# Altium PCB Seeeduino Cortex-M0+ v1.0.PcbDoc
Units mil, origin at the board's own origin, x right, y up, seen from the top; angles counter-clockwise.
Board outline 2700 x 2100 mil, 2 copper layers (Top, Bottom); 98 components, 76 nets, 339 pads, 260 vias.
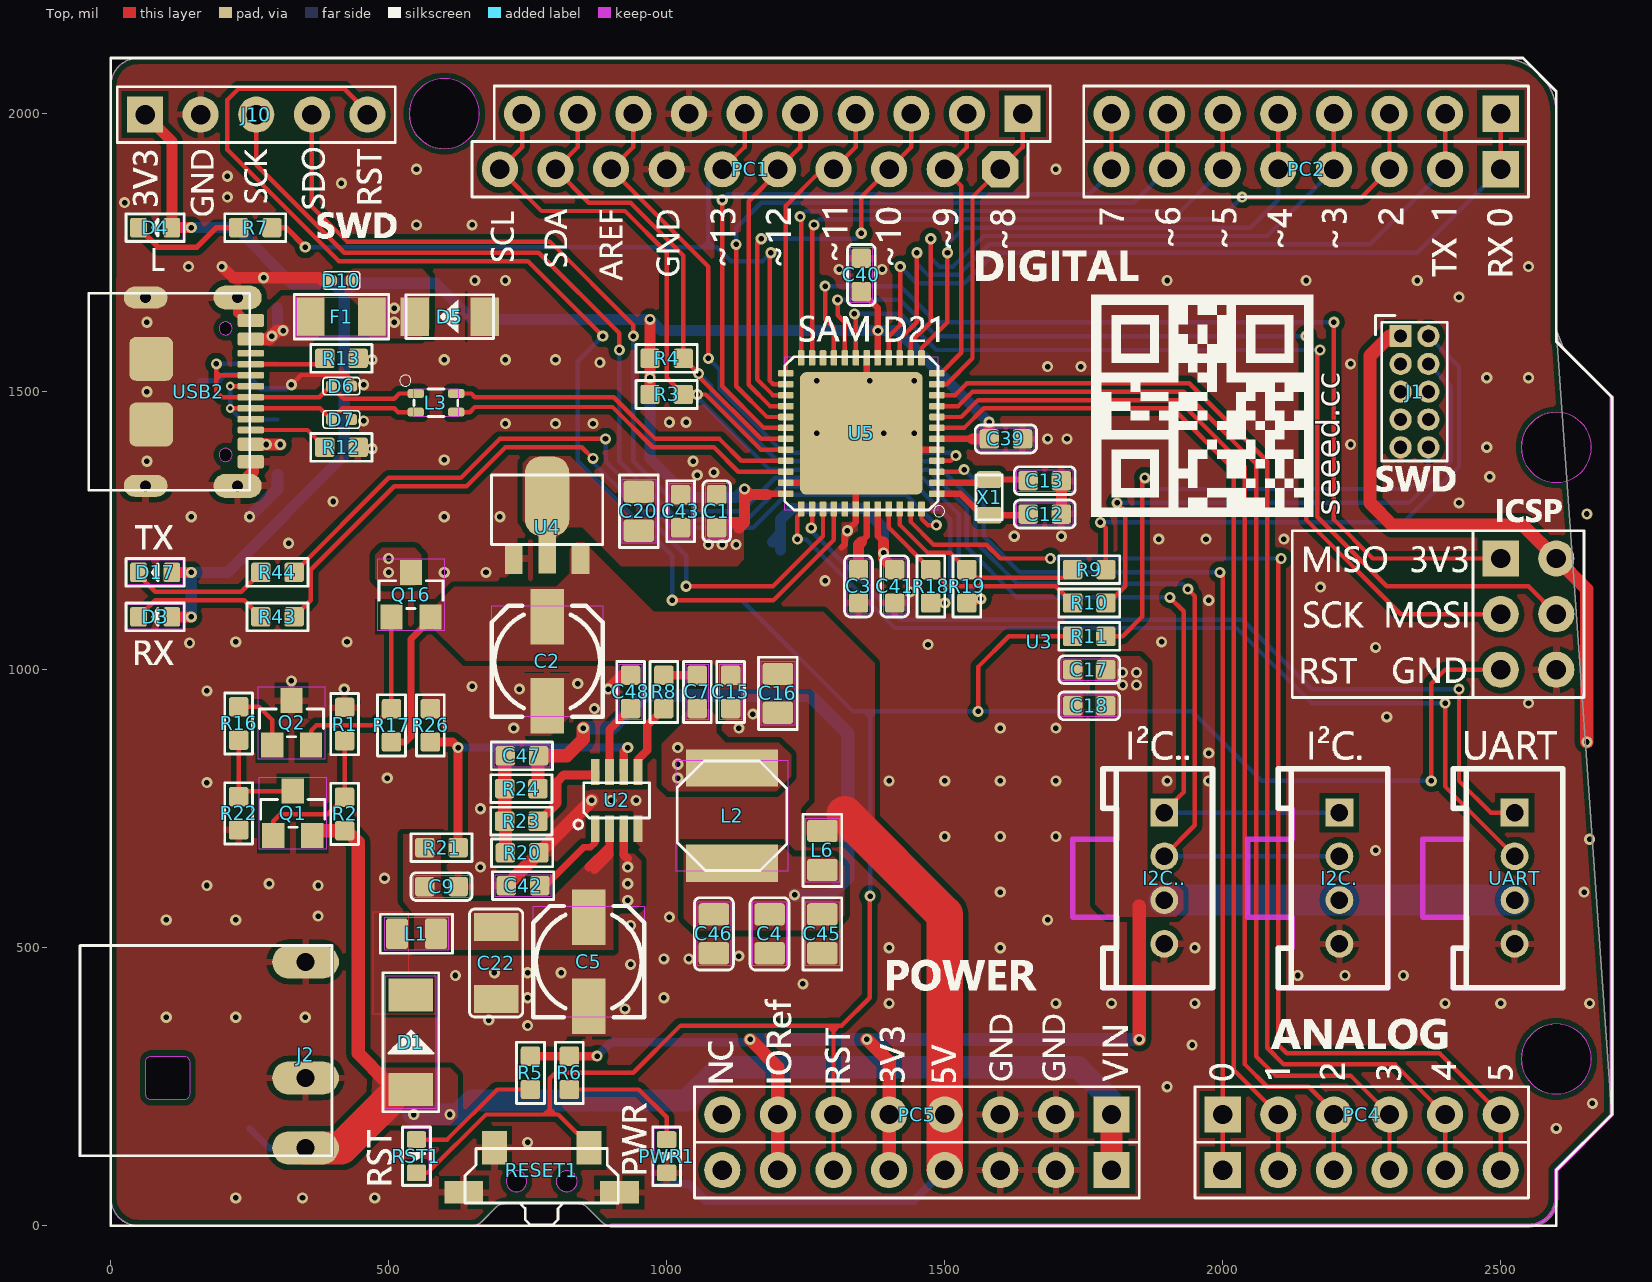
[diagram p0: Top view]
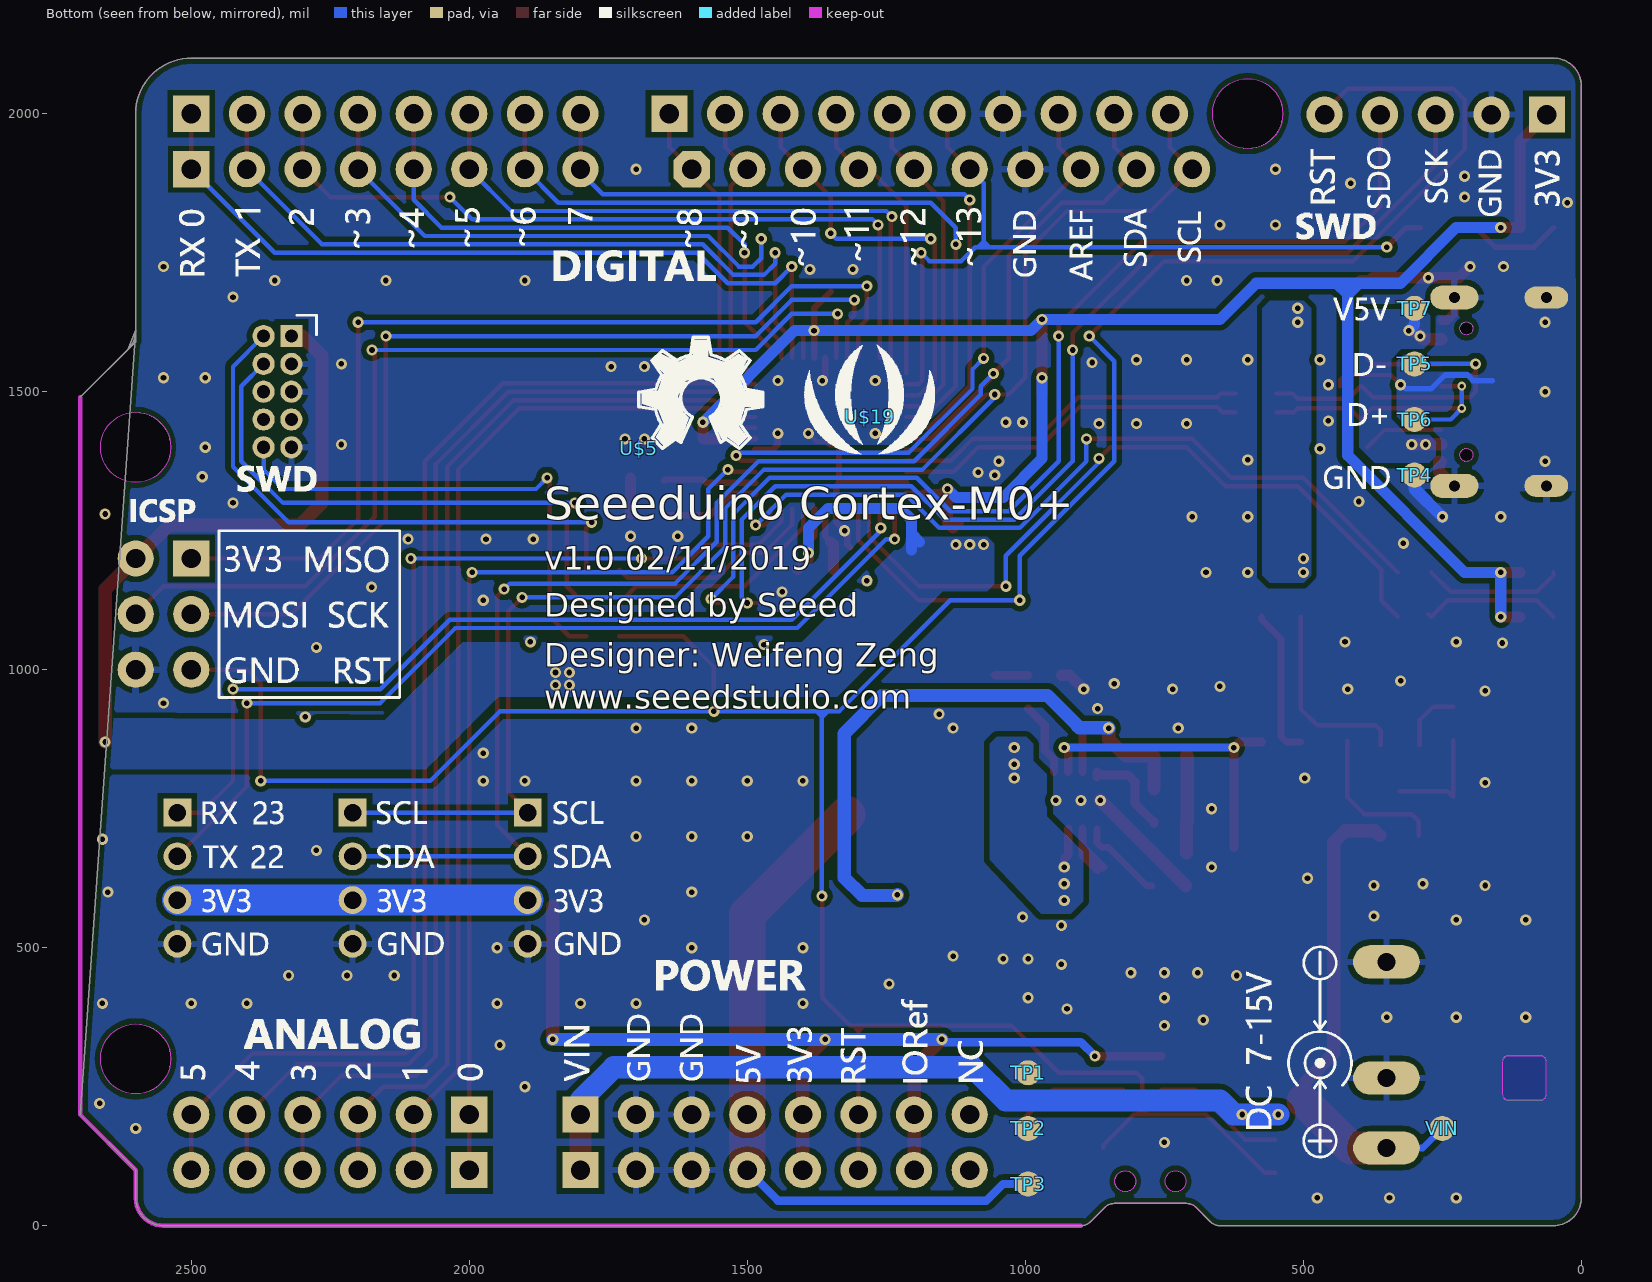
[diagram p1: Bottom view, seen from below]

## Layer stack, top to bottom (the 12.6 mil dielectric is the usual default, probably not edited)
Top Solder: solder mask 0.4, Solder Resist, Dk 3.5
Top: signal copper 1.378
Dielectric 1: dielectric 12.6, FR-4, Dk 4.8
Bottom: signal copper 1.378
Bottom Solder: solder mask 0.4, Solder Resist, Dk 3.5

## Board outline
2600,1610.71 ccw(c2650,1610.71) 2614.65,1575.35 2700,1490 2600,1590 2600,2000 ccw(c2500,2000) 2500,2100 50,2100 ccw(c50,2050) 0,2050 0,50 ccw(c50,50) 50,0 649.64,0 ccw(c649.64,25) 667.32,7.32 692.68,32.68 cw(c710.36,15) 710.36,40 839.64,40 cw(c839.64,15) 857.32,32.68 882.68,7.32 ccw(c900.36,25) 900.36,0 2550,0 ccw(c2550,50) 2600,50 2600,100 2700,200 2600,1610.71 ccw(c2650,1610.71)
cut-out: 600,1937 ccw(c600,2000) 663,2000 ccw(c600,2000) 600,2063 ccw(c600,2000) 537,2000 ccw(c600,2000)
cut-out: 2600,1337 ccw(c2600,1400) 2663,1400 ccw(c2600,1400) 2600,1463 ccw(c2600,1400) 2537,1400 ccw(c2600,1400)
cut-out: 2600,237 ccw(c2600,300) 2663,300 ccw(c2600,300) 2600,363 ccw(c2600,300) 2537,300 ccw(c2600,300)
cut-out: 73.11,226.42 cw(c73.11,236.42) 63.11,236.42 63.11,295.16 cw(c73.11,295.16) 73.11,305.16 131.85,305.16 cw(c131.85,295.16) 141.85,295.16 141.85,236.42 cw(c131.85,236.42) 131.85,226.42
cut-out: 729.72,61.3 ccw(c729.72,80) 748.42,80 ccw(c729.72,80) 729.72,98.7 ccw(c729.72,80) 711.02,80 ccw(c729.72,80)
cut-out: 820.28,61.3 ccw(c820.28,80) 838.98,80 ccw(c820.28,80) 820.28,98.7 ccw(c820.28,80) 801.58,80 ccw(c820.28,80)
cut-out: 206.69,1374.41 ccw(c206.69,1386.22) 218.5,1386.22 ccw(c206.69,1386.22) 206.69,1398.03 ccw(c206.69,1386.22) 194.88,1386.22 ccw(c206.69,1386.22)
cut-out: 206.69,1601.97 ccw(c206.69,1613.78) 218.5,1613.78 ccw(c206.69,1613.78) 206.69,1625.59 ccw(c206.69,1613.78) 194.88,1613.78 ccw(c206.69,1613.78)

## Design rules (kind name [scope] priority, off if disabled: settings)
BoardOutlineClearance mdCopperDimension [All] p1: gap=10 ignorepadtopadclearanceinfootprint=FALSE except(0: Arc-SplitContinuation Track-SplitContinuation SMDPad-SplitContinuation THPad-SplitContinuation Via-SplitContinuation Fill-SplitContinuation Poly-SplitContinuation Region-SplitContinuation Text-SplitContinuation)
Clearance Clearance_for_PolygonClass_Isolate_10 [InPolygonClass('Isolate_10') vs IsArc Or IsTrack Or IsPad Or IsVia Or IsFill Or IsRegion Or IsText] p1: gap=10 ignorepadtopadclearanceinfootprint=FALSE
Clearance "Clearance (Same Net)" [All] p2: gap=6 ignorepadtopadclearanceinfootprint=FALSE
Clearance Clearance_for_NetClass_usbvcc [InNetClass('usbvcc') vs InNetClass('usbvcc')] p3: gap=6 ignorepadtopadclearanceinfootprint=FALSE
Clearance Clearance_for_NetClass_gnd [InNetClass('gnd') vs InNetClass('gnd')] p4: gap=6 ignorepadtopadclearanceinfootprint=FALSE
Clearance Clearance_for_NetClass_power [InNetClass('power') vs InNetClass('power')] p5: gap=6 ignorepadtopadclearanceinfootprint=FALSE
Clearance [All] p6: gap=6 ignorepadtopadclearanceinfootprint=FALSE
HoleSize HoleSize_For_NetClass_usbvcc [InNetClass('usbvcc')] p1: absolutevalues=TRUE maxlimit=6 minlimit=6 maxpercent=80.000 minpercent=20.000
HoleSize HoleSize_For_NetClass_gnd [InNetClass('gnd')] p2: absolutevalues=TRUE maxlimit=6 minlimit=6 maxpercent=80.000 minpercent=20.000
HoleSize HoleSize_For_NetClass_power [InNetClass('power')] p3: absolutevalues=TRUE maxlimit=6 minlimit=6 maxpercent=80.000 minpercent=20.000
HoleSize [All] p4: absolutevalues=TRUE maxlimit=100000 minlimit=8 maxpercent=80.000 minpercent=20.000
HoleToHoleClearance mdDrill [All] p1: gap=10 allowstackedmicrovias=TRUE
MinimumSolderMaskSliver [All] p1 off: minsoldermaskwidth=10
PasteMaskExpansion Expansion_SMDPaste_OFF [InPadClass('SMDPaste_OFF')] p1: expansion=0
PasteMaskExpansion mlMinCreamFrame [All] p2: expansion=0
PolygonConnect PolygonConnect_For_PolygonThermal_ON_Width80000_Gap100000 [InPolygonClass('PolygonThermal_ON_Width80000_Gap100000') vs Not IsVia] p1: connectstyle=Relief reliefconductorwidth=8 reliefentries=4 polygonreliefangle="90 Angle" airgapwidth=10
PolygonConnect PolygonConnect_For_PolygonThermal_ON_Width120000_Gap100000 [InPolygonClass('PolygonThermal_ON_Width120000_Gap100000') vs Not IsVia] p2: connectstyle=Relief reliefconductorwidth=12 reliefentries=4 polygonreliefangle="90 Angle" airgapwidth=10
PolygonConnect PolygonConnect_For_PolygonThermal_OFF [InPolygonClass('PolygonThermal_OFF')] p3: connectstyle=Direct reliefconductorwidth=10 reliefentries=4 polygonreliefangle="90 Angle" airgapwidth=10
PolygonConnect ThermalVias [IsVia] p4: connectstyle=Direct reliefconductorwidth=10 reliefentries=4 polygonreliefangle="90 Angle" airgapwidth=10
PolygonConnect [All] p5: connectstyle=Relief reliefconductorwidth=10 reliefentries=4 polygonreliefangle="90 Angle" airgapwidth=10
RoutingVias [All] p1: holewidth=8 width=16 viastyle="Through Hole" minholewidth=8 minwidth=16 maxholewidth=100 maxwidth=100
SolderMaskExpansion Expansion_SMDSolder_OFF [InPadClass('SMDSolder_OFF')] p1: expansion=0
SolderMaskExpansion mlMinStopFrame [All] p2: expansion=2
Width Width_For_NetClass_usbvcc [InNetClass('usbvcc')] p1: maxlimit=10 minlimit=6 preferedwidth=6
Width Width_For_NetClass_gnd [InNetClass('gnd')] p2: maxlimit=10 minlimit=6 preferedwidth=6
Width Width_For_NetClass_power [InNetClass('power')] p3: maxlimit=10 minlimit=6 preferedwidth=6
Width [All] p4: maxlimit=10000 minlimit=6 preferedwidth=6
26 further rules are at their usual default settings.

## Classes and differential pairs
polygon class PolygonThermal_ON_Width80000_Gap100000: Polygon_1_Net_3V3 Polygon_3_Net_N$23
polygon class PolygonThermal_ON_Width120000_Gap100000: Polygon_3_Net_GND Polygon_7_Net_GND
polygon class PolygonThermal_OFF: Polygon_1_Net_5V Polygon_1_Net_EXT_PWR Polygon_1_Net_GND Polygon_1_Net_N$10 Polygon_1_Net_N$23 Polygon_1_Net_OUT1 Polygon_1_Net_PWR_IN Polygon_1_Net_USB5V Polygon_1_Net_V_USB Polygon_2_Net_3V3 Polygon_2_Net_GND Polygon_2_Net_N$23 Polygon_2_Net_USB5V Polygon_2_Net_V_USB Polygon_3_Net_3V3 Polygon_3_Net_USB5V Polygon_4_Net_GND Polygon_5_Net_GND Polygon_6_Net_GND Polygon_8_Net_GND Polygon_9_Net_GND Polygon_10_Net_GND Polygon_11_Net_GND
polygon class Isolate_10: Polygon_1_Net_3V3 Polygon_1_Net_5V Polygon_1_Net_EXT_PWR Polygon_1_Net_GND Polygon_1_Net_N$10 Polygon_1_Net_N$23 Polygon_1_Net_OUT1 Polygon_1_Net_PWR_IN Polygon_1_Net_USB5V Polygon_1_Net_V_USB Polygon_2_Net_3V3 Polygon_2_Net_GND Polygon_2_Net_N$23 Polygon_2_Net_USB5V Polygon_2_Net_V_USB Polygon_3_Net_3V3 Polygon_3_Net_GND Polygon_3_Net_N$23 Polygon_3_Net_USB5V Polygon_4_Net_GND Polygon_5_Net_GND Polygon_6_Net_GND Polygon_7_Net_GND Polygon_10_Net_GND Polygon_11_Net_GND
pad class SMDSolder_OFF: U4-2
pad class SMDPaste_OFF: TP1-T TP2-T TP3-T TP4-T TP5-T TP6-T TP7-T U4-2 U5-PAD VIN-T

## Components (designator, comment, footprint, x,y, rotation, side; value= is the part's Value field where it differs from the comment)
C1 "100nF" C0603#1 1090,1285 r0 top
C2 "22uF" ELECTRO-SMD-B-4.8MM 785,1015 r90 top
C3 "1uF" C0603#1 1345,1150 r180 top
C4 "10uF" C0805#1 1185,525 r180 top
C5 "22uF" ELECTRO-SMD-B-4.8MM 860,475 r90 top
C7 "100nF" C0603#2 1055,960 r90 top
C9 "100nF" C0603#1 595,610 r270 top
C12 "22p" C0603#1 1680,1280 r90 top
C13 "22p" C0603#1 1680,1340 r90 top
C15 "100nF" C0603#2 1115,960 r270 top
C16 "10uF" C0805#2 1200,957.5 r270 top
C17 "100nF" C0603#1 1760,1000 r90 top
C18 "1uF" C0603#1 1760,935 r90 top
C20 "10uF" C0805#2 950,1285 r90 top
C22 "22uF_16V" C1206 693.3,472.5 r270 top
C39 "100nF" C0603#1 1610,1415 r270 top
C40 "100nF" C0603#1 1350,1710 r0 top
C41 "100nF" C0603#1 1410,1150 r180 top
C42 "22nF" C0603#2 741.8,611.6 r0 top
C43 "100nF" C0603#2 1025,1285 r270 top
C45 "10uF" C0805#2 1280,525 r90 top
C46 "10uF" C0805#1 1085,525 r180 top
C47 "DNP" C0603#2 739.6,845 r180 top
C48 "100nF" C0603#2 935,960 r270 top
D1 "1N5819" D2010 540,330 r90 top
D3 "RED" LED-0603 80,1095 r0 top
D4 "BLUE" LED-0603 80,1795 r0 top
D5 "BZV55-C5V1" SOD80C 610,1635 r0 top
D6 "ESDPSA0402V05" ESD-0402 415,1510 r180 top
D7 "ESDPSA0402V05" ESD-0402 415,1450 r180 top
D10 "ESDPSA0402V05" ESD-0402 415,1700 r0 top
D17 "RED" LED-0603 80,1175 r0 top
F1 "1000mA" F1206 415,1635 r0 top
I2C. "4P-LEADED-2.0" 4P-LEADED-2.0 2210,625 r270 top
I2C.. "4P-LEADED-2.0" 4P-LEADED-2.0 1895,625 r270 top
J1 "DNP" H2X5-1.27 2345,1550 r0 top
J2 "DC JACK" DCJ3P-11.6X9.6X7.0MM -55,315 r270 top
J10 "DNP" H5-2.54 261.8,1998.4 r90 top
L1 "470R,2A" L0805 550,525 r0 top
L2 "10uH" L5040S 1117.5,737.5 r0 top
L3 "SRF2012-900YA" INT4-0.85-2X1.25X1.2MM 585,1480 r270 top
L6 "470R,2A" L0805 1280,675 r90 top
PC1 "DNP" 10P-2.54 1150,1900 r270 top
PC2 "DNP" 8P-2.54 2150,1900 r270 top
PC4 "DNP" 6P-2.54-65/35MIL 2250,200 r90 top
PC5 "DNP" 8P-2.54 1450,200 r270 top
PWR1 "GREEN" LED-0603 1000,125 r90 top
Q1 "MMBT3906LT3G" SOT23 327.6,741.7 r0 top
Q2 "MMBT3906LT3G" SOT23 325.4,904.4 r0 top
Q16 "CJ2305" SOT23 540,1135 r0 top
R1 "30K" R0603#1 420.7,902.2 r90 top
R2 "3.3K" R0603#1 420.7,740.6 r90 top
R3 "DNP" R0603#2 1000,1495 r180 top
R4 "DNP" R0603#2 1000,1560 r0 top
R5 "1k" R0603#2 755,275 r270 top
R6 "1k" R0603#2 825,275 r270 top
R7 "2k" R0603#2 260,1795 r180 top
R8 "10R" R0603#1 995,960 r90 top
R9 "0R" R0603#2 1760,1180 r0 top
R10 "0R" R0603#2 1760,1120 r0 top
R11 "0R" R0603#2 1760,1060 r0 top
R12 "5.1k" R0603#2 415,1400 r180 top
R13 "5.1k" R0603#2 415,1560 r0 top
R16 "1k" R0603#1 230.1,903.3 r90 top
R17 "100K" R0603#1 505,900 r270 top
R18 "0R" R0603#2 1475,1150 r90 top
R19 "0R" R0603#2 1540,1150 r90 top
R20 "7.5k_1%" R0603#1 740,670.7 r180 top
R21 "100K" R0603#1 595,680 r180 top
R22 "10K" R0603#1 230.1,741.7 r270 top
R23 "33k" R0603#1 738.5,727.5 r180 top
R24 "39k_1%" R0603#1 738.5,786.1 r180 top
R26 "24K" R0603#1 575,900 r90 top
R43 "2k" R0603#2 300,1095 r180 top
R44 "2k" R0603#2 300,1175 r180 top
RESET1 "TS-118E" 4P-SMD-7X3.5X3.5H 775,80 r0 top
RST1 "RED" LED-0603 550,125 r90 top
TP1 "" TP-D45MIL 995,275 r270 bottom
TP2 "" TP-D45MIL 995,175 r270 bottom
TP3 "" TP-D45MIL 995,75 r270 bottom
TP4 "" TP-D45MIL 300,1350 r180 bottom
TP5 "" TP-D45MIL 300,1550 r180 bottom
TP6 "" TP-D45MIL 300,1450 r180 bottom
TP7 "" TP-D45MIL 300,1650 r180 bottom
U2 "" TSOT23-8 910,765 r0 top
U3 "" ARDUINO-38P 0,0 r0 top
U4 "CJA1117B-3.3" SOT-89 785,1275 r0 top
U5 "MCU-ATSAMD21-QFN48" QFN48-7X7 1350,1425 r180 top
U$1 "" SEEEDSTUDIO-PCB-FRAME -361.1,-315 r0 top
U$5 "" OSHW_FILLX200_NOTEXT 1695,1398 r180 bottom
U$6 "" SEEEDSTUDIO-PCB-FRAME -364.78,-1310 r0 top
U$8 "" SEEEDSTUDIO-PCB-FRAME -358.55,-950 r0 top
U$19 "" SEEED-SILK-TNAME-280*268MIL 1280,1455 r180 bottom
U$23 "" SEEEDSTUDIO-PCB-FRAME -362.33,-610 r0 top
UART "4P-LEADED-2.0" 4P-LEADED-2.0 2525,625 r270 top
USB2 "TypeC" USB2.0-TYPE-C 250,1500 r0 top
VIN "" TP-D45MIL 250,175 r180 bottom
X1 "32,768Khz_SMD" X2-SMD-L2.0X1.2X0.55MM 1580,1310 r270 top

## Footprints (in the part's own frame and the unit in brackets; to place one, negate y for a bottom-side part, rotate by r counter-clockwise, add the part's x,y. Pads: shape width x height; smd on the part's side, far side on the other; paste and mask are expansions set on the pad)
4P-LEADED-2.0 [mil] "4P-LEADED-2.0"
  rect 50x50 / inner rect 60x60 / far side rect 50x50 hole 31.5: 1(-118.11,0)
  round 50 / inner round 60 / far side round 50 hole 31.5: 2(-39.37,0) 3(39.37,0) 4(118.11,0)
  Top keep-out lines w10: 196.85,-110.24 196.85,86.61 -196.85,86.61 -196.85,-110.24 ; 195,-110 125,-110 125,-85 70,-85 70,-165 -70,-165 -70,-85 -125,-85 -125,-110 -195,-110
  silkscreen extent -197,-110 197,87
4P-SMD-7X3.5X3.5H [mil] "4P-SMD-7X3.5X3.5H"
  rect 45x60 smd: 1(-85,60) 2(85,60)
  rect 70x40 smd: S1(-140,-20) S2(140,-20)
  silkscreen extent -138,-79 138,59
6P-2.54-65/35MIL [mil] "6P-2.54-65/35MIL"
  rect 65x65 / inner rect 60x60 / far side rect 65x65 hole 35: 1(0,250)
  round 65 / inner round 60 / far side round 65 hole 35: 2(0,150) 3(0,50) 4(0,-50) 5(0,-150) 6(0,-250)
  Top keep-out region: -50,-300 -50,300 50,300 50,-300
  Top keep-out lines w0: -50,300 -50,-300 50,-300 50,300 -50,300
  silkscreen extent -50,-300 50,300
8P-2.54 [mil] "8P-2.54"
  rect 65x65 / inner rect 60x60 / far side rect 65x65 hole 35: 1(0,350)
  round 65 / inner round 60 / far side round 65 hole 35: 2(0,250) 3(0,150) 4(0,50) 5(0,-50) 6(0,-150) 7(0,-250) 8(0,-350)
  Top keep-out region: -50,-400 -50,400 50,400 50,-400
  Top keep-out lines w0: 50,-400 -50,-400 -50,400 50,400 50,-400
  silkscreen extent -50,-400 50,400
10P-2.54 [mil] "10P-2.54"
  oct 65x65 / inner oct 60x60 / far side oct 65x65 hole 35: 1(0,450)
  round 65 / inner round 60 / far side round 65 hole 35: 2(0,350) 3(0,250) 4(0,150) 5(0,50) 6(0,-50) 7(0,-150) 8(0,-250) 9(0,-350) 10(0,-450)
  Top keep-out region: -50,-500 -50,500 50,500 50,-500
  Top keep-out lines w0: 50,-500 -50,-500 -50,500 50,500 50,-500
  silkscreen extent -50,-500 50,500
ARDUINO-38P [mil] "ARDUINO-38P"
  rect 65x65 / inner rect 60x60 / far side rect 65x65 hole 35: 1(2500,2000) 9(1640,2000) 19(2000,100) 25(1800,100) 38(2500,1200)
  round 65 / inner round 60 / far side round 65 hole 35: 2(2400,2000) 3(2300,2000) 4(2200,2000) 5(2100,2000) 6(2000,2000) 7(1900,2000) 8(1800,2000) 10(1540,2000) 11(1440,2000) 12(1340,2000) 13(1240,2000) 14(1140,2000) 15(1040,2000) 16(940,2000) 17(840,2000) 18(740,2000) 20(2100,100) 21(2200,100) 22(2300,100) 23(2400,100) 24(2500,100) 26(1700,100) 27(1600,100) 28(1500,100) 29(1400,100) 30(1300,100) 31(1200,100) 32(1100,100) 33(2600,1200) 34(2600,1100) 35(2600,1000) 36(2500,1000) 37(2500,1100)
  silkscreen extent 0,0 2700,2100
C0603#1 [mil] "C0603"
  rrect25% 35x35 smd: 1(0,30) 2(0,-30)
  Top keep-out region: -20,50 20,50 20,-50 -20,-50
  silkscreen extent -25,-55 25,55
C0603#2 [mil] "C0603"
  rrect25% 35x35 smd: 1(-30,0) 2(30,0)
  Top keep-out region: -50,-20 -50,20 50,20 50,-20
  silkscreen extent -55,-25 55,25
C0805#1 [mil] "C0805"
  rrect25% 55x40 smd: 1(0,35) 2(0,-35)
  Top keep-out region: -30,57.5 30,57.5 30,-57.5 -30,-57.5
  silkscreen extent -35,-65 35,65
C0805#2 [mil] "C0805"
  rrect25% 40x55 smd: 1(-35,0) 2(35,0)
  Top keep-out region: -57.5,-30 -57.5,30 57.5,30 57.5,-30
  silkscreen extent -65,-35 65,35
C1206 [mil] "C1206"
  rect 50x80 smd: 1(-65,0) 2(65,0)
  silkscreen extent -97,-48 97,48
D2010 [mil] "D2010"
  rect 60x80 smd: +(-85,0) -(85,0)
  Top keep-out region: -120,-45 -120,45 120,45 120,-45
  silkscreen extent -125,-50 125,50
DCJ3P-11.6X9.6X7.0MM [mil] "DCJ3P-11.6X9.6X7.0MM"
  oval 60x120 / inner round 60 / far side oval 60x120 hole 32: +(175.2,405.51) -(-159.45,405.51) CDN(49.21,405.51)
  Top keep-out region: -190,0 -190,455 190,455 190,0
  silkscreen extent -189,0 189,453
ELECTRO-SMD-B-4.8MM [mil] "ELECTRO-SMD-B-4.8MM"
  rect 100x60 smd: +(80,0) -(-80,0)
  Top keep-out region: -100,-100 -100,100 100,100 100,-100
  silkscreen extent -100,-100 100,100
ESD-0402 [mil] "ESD-0402"
  rrect50% 19.69x19.69 smd: 1(-18.21,0) 2(18.21,0)
  silkscreen extent -33,-16 33,16
F1206 [mil] "F1206"
  rect 50x70 smd: 1(-55,0) 2(55,0)
  Top keep-out region: -80,-35 -80,35 80,35 80,-35
  silkscreen extent -85,-40 85,40
H2X5-1.27 [mil] "H2X5-1.27"
  rect 39.92x39.92 / inner rect 60x60 / far side rect 39.92x39.92 hole 23.62: 1(-25,50)
  round 39.92 / inner round 60 / far side round 39.92 hole 23.62: 2(25,50) 3(-25,0) 4(25,0) 5(-25,-50) 6(25,-50) 7(-25,-100) 8(25,-100) 9(-25,-150) 10(25,-150)
  Top keep-out region: -60,-175 -60,75 60,75 60,-175
  silkscreen extent -59,-175 59,75
H5-2.54 [mil] "H5-2.54"
  rect 65x65 / inner rect 60x60 / far side rect 65x65 hole 35: 1(0,200)
  round 65 / inner round 60 / far side round 65 hole 35: 2(0,100) 3(0,0) 4(0,-100) 5(0,-200)
  Top keep-out region: -50,-250 -50,250 50,250 50,-250
  Top keep-out lines w0: -50,250 -50,-250 50,-250 50,250 -50,250
  silkscreen extent -50,-250 50,250
INT4-0.85-2X1.25X1.2MM [mil] "INT4-0.85-2X1.25X1.2MM"
  rrect50% 15.75x29.53 smd: 1(-16.73,-36.42) 2(-16.73,36.42) 3(16.73,36.42) 4(16.73,-36.42)
  Top keep-out region: 25,-40 -25,-40 -25,40 25,40
  silkscreen extent -50,-65 25,39
L0805 [mil] "L0805"
  rrect25% 40x55 smd: 1(-35,0) 2(35,0)
  Top keep-out region: -57.5,-30 -57.5,30 57.5,30 57.5,-30
  silkscreen extent -65,-35 65,35
L5040S [mm] "L5040S"
  rect 4.2x1.7 smd: 1(0,2.175) 2(0,-2.175)
  Top keep-out region: -2.54,-2.54 -2.54,2.54 2.54,2.54 2.54,-2.54
  silkscreen extent -2.5,-2.5 2.5,2.5
LED-0603 [mil] "LED-0603"
  rrect25% 30x35 smd: +(30,0) -(-30,0)
  Top keep-out region: 50,22.5 50,-22.5 -50,-22.5 -50,22.5
  silkscreen extent -52,-25 52,25
OSHW_FILLX200_NOTEXT [mil] "OSHW_FILLX200_NOTEXT"
  silkscreen extent 0,0 223,200
QFN48-7X7 [mil] "QFN48-7X7"
  rrect30% 27.56x11.81 smd: 1(-135.83,108.27) 2(-135.83,88.58) 3(-135.83,68.9) 4(-135.83,49.21) 5(-135.83,29.53) 6(-135.83,9.84) 7(-135.83,-9.84) 8(-135.83,-29.53) 9(-135.83,-49.21) 10(-135.83,-68.9) 11(-135.83,-88.58) 12(-135.83,-108.27) 25(135.83,-108.27) 26(135.83,-88.58) 27(135.83,-68.9) 28(135.83,-49.21) 29(135.83,-29.53) 30(135.83,-9.84) 31(135.83,9.84) 32(135.83,29.53) 33(135.83,49.21) 34(135.83,68.9) 35(135.83,88.58) 36(135.83,108.27)
  rrect30% 11.81x27.56 smd: 13(-108.27,-135.83) 14(-88.58,-135.83) 15(-68.9,-135.83) 16(-49.21,-135.83) 17(-29.53,-135.83) 18(-9.84,-135.83) 19(9.84,-135.83) 20(29.53,-135.83) 21(49.21,-135.83) 22(68.9,-135.83) 23(88.58,-135.83) 24(108.27,-135.83) 37(108.27,135.83) 38(88.58,135.83) 39(68.9,135.83) 40(49.21,135.83) 41(29.53,135.83) 42(9.84,135.83) 43(-9.84,135.83) 44(-29.53,135.83) 45(-49.21,135.83) 46(-68.9,135.83) 47(-88.58,135.83) 48(-108.27,135.83)
  rrect10% 220.47x220.47 smd paste-110.23: PAD(0,0)
  Top keep-out region: -137.8,137.8 137.8,137.8 137.8,-137.8 -137.8,-137.8
  silkscreen extent -150,-138 138,150
R0603#1 [mil] "R0603"
  rrect25% 35x35 smd: 1(-30,0) 2(30,0)
  silkscreen extent -55,-25 55,25
R0603#2 [mil] "R0603"
  rrect25% 35x35 smd: 1(-30,0) 2(30,0)
  Top keep-out region: -55,-25 -55,25 55,25 55,-25
  silkscreen extent -55,-25 55,25
SEEED-SILK-TNAME-280*268MIL [mil] "SEEED-SILK-TNAME-280*268MIL"
  silkscreen extent -118,-68 118,130
SEEEDSTUDIO-PCB-FRAME [mil] "SEEEDSTUDIO-PCB-FRAME"
SOD80C [mil] "SOD80C"
  rect 51.18x69.69 smd: 1(62.99,0) 2(-62.99,0)
  Top keep-out region: -80,-40 -80,40 80,40 80,-40
  silkscreen extent -79,-39 79,39
SOT23 [mil] "SOT23"
  rect 40x45 smd: 1(-35,-40) 2(35,-40) 3(0,40)
  Top keep-out region: -60,-65 -60,65 60,65 60,-65
  silkscreen extent -58,-25 58,25
SOT-89 [mil] "SOT-89"
  rect 31.5x55.12 smd: 1(-60,-75) 3(60,-75)
  rect 31.5x74.8 smd paste-37.4 mask-37.4: 2(0,-65)
  rrect75% 80x143.7 smd: 4(0,37.01)
  silkscreen extent -100,-50 100,75
TP-D45MIL [mil] "TP-D45MIL"
  rrect100% 45x45 smd paste-22.5: T(0,0)
TSOT23-8 [mil] "TSOT23-8"
  rect 15.75x47.24 smd: 1(-38.39,-51.18) 2(-12.8,-51.18) 3(12.8,-51.18) 4(38.39,-51.18) 5(38.39,51.18) 6(12.8,51.18) 7(-12.8,51.18) 8(-38.39,51.18)
  silkscreen extent -77,-51 59,32
USB2.0-TYPE-C [mm] "USB2.0-TYPE-C"
  rrect30% 1.2x0.6 smd: A1_B12(0.05,3.25) A4_B9(0.05,2.4) B1_A12(0.05,-3.2) B4_A9(0.05,-2.4)
  rrect30% 1.2x0.3 smd: A5(0.05,1.25) A6(0.05,0.25) A7(0.05,-0.25) A8(0.05,-1.25) B5(0.05,-1.75) B6(0.05,-0.75) B7(0.05,0.75) B8(0.05,1.75)
  oval 2x1 / inner round 1.524 / far side oval 2x1 hole 0.5: S1(-4.75,4.3) S2(-4.75,-4.3)
  oval 2.2x1.1 / inner round 1.524 / far side oval 2.2x1.1 hole 0.5: S3(-0.55,4.3) S4(-0.55,-4.3)
  rrect30% 2x2 smd: S5(-4.5,1.5) S6(-4.5,-1.5)
  silkscreen extent -7.35,-4.5 0,4.5
X2-SMD-L2.0X1.2X0.55MM [mil] "X2-SMD-L2.0X1.2X0.55MM"
  rrect30% 30x45 smd: 1(-32,0) 2(32,0)
  silkscreen extent -40,-24 40,24

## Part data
C1 C3 C7 C9 C12 C13 C15 C17 C18 C39 C40 C41 C42 C43 C47 C48: library part C0603
C2 C5: library part ELECTRO-SMD-B-4.8MM
C4 C16 C20 C45 C46: library part C0805
C22: library part C1206
D1: library part D2010
D3 D4 D17 PWR1 RST1: library part LED-0603
D5: library part SOD80C
D6 D7 D10: library part ESD-0402
F1: library part F1206
J1: library part H2X5-1.27
J2: library part DCJ3P-11.6X9.6X7.0MM
J10: library part H5-2.54
L1 L6: library part L0805
L2: library part L5040S
L3: library part INT4-0.85-2X1.25X1.2MM
PC1: library part 10P-2.54
PC2 PC5: library part 8P-2.54
PC4: library part 6P-2.54-65/35MIL
Q1 Q2 Q16: library part SOT23
R1 R2 R3 R4 R5 R6 R7 R8 R9 R10 R11 R12 R13 R16 R17 R18 R19 R20 R21 R22 R23 R24 R26 R43 R44: library part R0603
RESET1: library part 4P-SMD-7X3.5X3.5H
TP1 TP2 TP3 TP4 TP5 TP6 TP7 VIN: library part TP-D45MIL
U2: library part TSOT23-8
U3: library part ARDUINO-38P
U4: library part SOT-89
U5: library part QFN48-7X7
U$1 U$6 U$8 U$23: library part SEEEDSTUDIO-PCB-FRAME
U$5: library part OSHW_FILLX200_NOTEXT
U$19: library part SEEED-SILK-TNAME-280*268MIL
USB2: library part USB2.0-TYPE-C
X1: library part X2-SMD-L2.0X1.2X0.55MM

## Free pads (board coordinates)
  round 23.62 hole 23.62 unplated: MH1(206.69,1386.22) MH2(206.69,1613.78)
  round 126 hole 126 unplated: MH1(600,2000) MH2(2600,1400) MH3(2600,300)
  round 37.4 hole 37.4 unplated: MH1(729.72,80) MH2(820.28,80)

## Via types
v1: diameter 20/20 (per signal layer), hole 10, Top to Bottom, tented both sides, 258 vias
v2: diameter 16/16 (per signal layer), hole 8, Top to Bottom, tented both sides, 2 vias

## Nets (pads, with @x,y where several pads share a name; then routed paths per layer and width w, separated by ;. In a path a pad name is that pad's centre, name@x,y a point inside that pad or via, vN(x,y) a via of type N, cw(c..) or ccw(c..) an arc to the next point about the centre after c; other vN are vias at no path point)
3V3: C1.2 C17.2 C18.2 C20.1 C39.2 C40.2 C41.2 C43.2 D3.+ D4.+ D17.+ I2C..3 I2C...3 J1.1 J10.1 PC5.5 PC5.7 R3.2 R4.1 R5.1 R6.1 U3.29 U3.31 U3.33 U4.2 U4.4 U5.6 U5.17 U5.36 U5.44 UART.3 | length 7655.1
  Top w11.5: 1180,1315 1181.73,1316.73 U5.36 ; C40.2 1379.53,1650.47 1379.53,1609.53 U5.17 ; U5.44 1379.53,1240.47 1390,1230 ; U5.6 1549.84,1415.16 1550,1415
  Top w15: R5.1 v1(875,305)
  Top w20: J10.1 110,1950.2 D4.+ v1(145,1795) ; D3.+ v1(145,1095) ; D17.+ v1(145,1175) ; R3.2 v1(970,1525) v1(970,1630) ; 1120,1265 1140,1265 ; 1130,1255 1140,1265 ; 1180,1315 1150,1315 ; v1@1379.53,1609.53 v1(1380,1610) ; 1390,1230 v1(1390,1210) 1390,1200 C41.2 ; 1550,1415 C39.2 v1(1580,1445) ; 1140,1265 1140,1305 ; 1140,1305 1150,1315 ; 1140,1305 1140,1315 ; 1140,1315 1150,1315 ; 1140,1315 v1(1140,1325) 1150,1315
  Top w24: v1(1150,335) 1200,285 U3.31 ; v1(1360,335) 1400,295 U3.29 ; v1(1850,335) 1850,575 ; J1.1 2300,1600 2265,1565 2265,1300 2305,1260 2540,1260 U3.33 2655,1145 v1(2655,870)
  Bottom w15: v1(875,305) 900,330 1145,330 v1(1150,335)
  Bottom w20: v1(145,1095) v1(145,1175) 210,1175 420,1385 420,1675 ; v1(145,1795) 225,1795 325,1695 400,1695 ; v1(970,1525) 970,1379.64 1039.64,1310 1125,1310 v1(1140,1325) ; 1190,1230 1205,1245 ; 1205,1215 1205,1245 ; v1(1390,1210) 1390,1255 1355,1290 1225,1290 1205,1270 1205,1245 ; v1(1580,1445) 1415,1610 v1(1380,1610) 990,1610 v1(970,1630) 650,1630 585,1695 440,1695 ; 400,1695 420,1675 ; 400,1695 420,1695 ; 420,1675 440,1695 ; 420,1675 420,1695 ; 420,1695 440,1695
  Bottom w24: v1(1150,335) v1(1360,335) v1(1850,335)
  Bottom w56: I2C...3 UART.3
  other v1: 1820,972.5 1845,972.5 1820,995 1845,995 1075,1225 1100,1225 1125,1225
5V: C2.+ C15.1 C16.1 L6.2 PC5.4 Q16.2 R17.2 TP3.T U3.28 U4.3 | length 1523.4
  Top w12: R17.2 530,870 540,880 540,1055 575,1090 Q16.2
  Top w66: 1320,740 1500,560 PC5.4 U3.28
  Bottom w15: TP3.T 1040,75 1070,45 1445,45 U3.28
AGND: 
D+: D7.2 L3.4 TP6.T USB2.A6 USB2.B6 | length 523.6
  Top w8: v2(215,1470) 215.47,1470.47 USB2.B6 376.32,1470.47 D7.2 416.79,1470 510,1470 516.73,1463.27 L3.4 ; v2(215,1510) 215.16,1509.84 USB2.A6
  Bottom w8: v2(215,1510) v2(215,1470) 235,1450 TP6.T
D-: D6.2 L3.1 TP5.T USB2.A7 USB2.B7 | length 623.9
  Top w8: v1(190,1550) 190,1535 ; USB2.B7 197.03,1529.53 ; L3.1 519.23,1496.73 510,1487.5 419.29,1487.5 D6.2 395,1510 375.16,1490.16 USB2.A7 199.84,1490.16 190,1500 190,1522.5 ; 190,1522.5 197.03,1529.53 ; 190,1522.5 190,1530 ; 190,1530 190.47,1529.53 195.47,1529.53 ; 190,1530 190,1535 ; 190,1535 195.47,1529.53 ; 195.47,1529.53 197.03,1529.53
  Bottom w8: v1(190,1550) TP5.T
EXT_PWR: D1.+ J2.+ PC5.1 Q1.2 R2.1 U3.25 VIN.T | length 2285.3
  Top w24: Q1.2 371.5,710.6 R2.1 424.4,710.6 445,690 445,310 495,260
  Top w40: U3.25 PC5.1
  Top w60: J2.+ 414.8,139.8 D1.+@500,225
  Bottom w12: VIN.T 285.2,139.8 J2.+
  Bottom w40: v1(545,200) v1(610,200) 625,200 650,225 1035,225 1095,285 1740,285 1800,225 PC5.1
EXT_PWR_SIG: Q2.2 Q16.1 R17.1 | length 352
  Top w8: Q2.2 360.4,890.4 370,900 475,900 R17.1 Q16.1
GND: C1.1 C2.- C3.1 C4.1 C5.- C9.1 C12.2 C13.2 C15.2 C16.2 C17.1 C18.1 C20.2 C22.2 C39.1 C40.1 C41.1 C42.1 C43.1 C45.1 C46.1 C48.1 D5.1 D6.1 D7.1 D10.1 I2C..4 I2C...4 J1.3 J1.5 J1.9 J2.- J2.CDN J10.2 PC1.7 PC5.2 PC5.3 PWR1.- Q2.3 R1.2 R12.1 R13.2 R20.1 R22.2 R26.2 RESET1.1 RESET1.S1 RESET1.S2 TP4.T U2.4 U3.15 U3.26 U3.27 U3.35 U4.1 U5.5 U5.18 U5.35 U5.42 U5.PAD UART.4 USB2.A1_B12 USB2.B1_A12 USB2.S1 USB2.S2 USB2.S3 USB2.S4 USB2.S5 USB2.S6 | length 1560.2
  Top w8: v1(325,1512.5) 342.5,1530 425,1530 433.21,1521.79 D6.1 ; U5.PAD@1350,1410 1375,1410 v1(1390,1425) ; U5.PAD@1359.84,1529.84 1359.84,1525.16 v1(1365,1520)
  Top w11.5: U5.35 1266.42,1336.42 1270,1340 U5.PAD@1335,1340 ; 1315,1220 1320,1225 1320,1245 v1(1325,1250) 1340.16,1265.16 1340.16,1329.84 1335,1335 U5.PAD@1335,1340 ; U5.PAD@1335,1410 U5.PAD@1335,1340 ; U5.PAD@1359.84,1529.84 U5.18 ; v1(1445,1425) 1445,1405 1454.53,1395.47 U5.5
  Top w16: USB2.S3 228.35,1641.65 242.05,1627.95 USB2.A1_B12
  Top w20: v1(200,1725) 220,1705 v1(275,1705) 375,1705 380,1700 D10.1 ; USB2.B1_A12 USB2.B1_A12@255.98,1374.02 ; v1(895,965) 920,990 C48.1 ; U5.PAD@1335,1410 U5.PAD@1350,1410 ; C12.2 C13.2@1710,1345
  Top w22: USB2.S4 229.06,1330 230,1330 255.98,1355.98 USB2.B1_A12@255.98,1374.02
  Top w24: C42.1 711.8,611.8 770,670 R20.1 770.7,670.7 v1(865,765)
  Bottom w10: 160,1520 195,1520 205,1530 245,1530 270,1505 315,1505 322.5,1512.5 v1(325,1512.5)
  Bottom w22: v1(250,1275) 300,1325 TP4.T
  other v1: 225,50 345,50 475,50 750,150 2600,175 2665,220 1900,250 1945,325 750,360 680,370 100,375 225,375 350,375 925,390 1400,400 1700,400 1800,400 1950,400 2400,400 2500,400 2660,400 750,410 995,410 1245,435 620,450 2135,450 2220,450 2325,450 690,455 750,455 810,455 935,470 995,480 1040,480 1130,485 1400,500 1600,500 1950,500 935,540 100,550 225,550 1685,550 1005,555 373.1,556.9 1600,600 2650,600 173.1,611.9 373.1,611.9 285,615 492.5,625 665,645 2275,675 2660,695 1500,700 1600,700 1700,700 665,750 900,765 945,765 173.1,796.9 1400,800 1500,800 1600,800 1700,800 1900,800 1975,800 497.5,805 1975,850 725,895 1130,895 1600,895 1700,895 2295,915 1155,920 870,930 2550,940 173.1,961.9 420,965 735,965 650,970 840,975 325,980 2275,1040 1470,1045 142,1048 225,1050 425,1050 1890,1050 1975,1125 1437.5,1140 2175.72,1148.51 1285,1160 600,1175 675,1175 320,1227.5 1885,1235 1970,1235 2110,1235 1625,1240 1710,1240 145,1275 600,1275 700,1275 2655,1280 2425,1300 400,1302.5 2480.26,1347.05 1055,1350 1085,1355 65,1375 1047.5,1375 600,1377.5 470,1397.5 2475,1400 2230,1405 1685,1415 1720,1415 1270,1425 710,1442.5 800,1442.5 867.5,1442.5 1005,1445 1035,1445 455,1447.5 65,1500 455,1512.5 1270,1520 1445,1520 2475,1525 2550,1525 1685,1545 1745,1545 2230,1550 880,1552.5 470,1557.5 600,1557.5 710,1557.5 800,1557.5 65,1625 2425,1670 655,1700 710,1700 1900,1700 2150,1700 2350,1700 1310,1720 1387.5,1720 140,1725 2550,1725 550,1800 650,1800 25,1840 210,1850 415,1875 210,1887.5 550,1900 1700,1900
N$1: C13.1 U5.2 X1.1 | length 167.3
  Top w11.5: U5.2 1574.42,1336.42 X1.1 1648,1342 C13.1
N$2: R21.1 R26.1 U2.6 | length 585.9
  Top w15: U2.6 922.8,852.8 v1(930,860)
  Top w16: R26.1 615,870 v1(625,860) R21.1
  Bottom w15: v1(625,860) v1(930,860)
N$3: C3.2 U5.43 | length 115.3
  Top w11.5: 1350,1230 1359.84,1239.84 U5.43
  Top w20: C3.2 1345,1225 1350,1230
N$4: D3.- R43.2 | length 251.9
  Top w8: D3.- 80,1125 240,1125 R43.2 R43.2@275,1100
N$5: Q1.1 R1.1 R2.2 | length 273.4
  Top w8: Q1.1 292.6,727.6 305,740 390.1,740 R2.2 R1.1
N$6: C12.1 U5.1 X1.2 | length 181
  Top w11.5: U5.1 1528.27,1316.73 1567,1278 X1.2 1648,1278 C12.1
N$8: Q2.1 R16.2 | length 115.3
  Top w8: R16.2 266.7,933.3 290.4,909.6 Q2.1
N$9: Q1.3 R16.1 R22.1 | length 203.2
  Top w8: R16.1 R22.1 240.1,781.7 Q1.3
N$10: D1.- L1.1
N$12: D17.- R44.2 | length 251.9
  Top w8: D17.- 50,1170 80,1140 235,1140 R44.2
N$13: J1.2 R9.2 | length 1033.3
  Top w8: v1(1780,1265) 1790,1255 R9.2
  Bottom w8: v1(1780,1265) 2325,1265 2425,1365 2425,1545 J1.2
N$14: J1.4 R10.2 | length 1026.3
  Top w8: R10.2 1795,1120 1825,1150 1825,1285 v1(1810,1300)
  Bottom w8: v1(1810,1300) 2335,1300 2410,1375 2410,1510 J1.4
N$15: R5.2 RST1.+ | length 242.3
  Top w8: RST1.+ 605,155 695,245 R5.2
N$16: PWR1.+ R6.2 | length 235.7
  Top w8: R6.2 950,245 1000,195 PWR1.+
N$17: J1.10 R11.2 | length 904.4
  Top w8: R11.2 1820,1060 1855,1095 1855,1340 v1(1860,1345)
  Bottom w8: v1(1860,1345) 1880,1325 2335,1325 2370,1360 J1.10
N$18: D4.- R7.2 | length 209
  Top w10: D4.- 85,1760 155,1760 190,1795 R7.2
N$19: R12.2 USB2.B5 | length 145.9
  Top w8: USB2.B5 353.9,1431.1 R12.2
N$20: C48.2 U2.7 | length 129.5
  Top w15: U2.7 897.2,892.2 C48.2
N$21: C42.2 U2.1 | length 156.7
  Top w12: C42.2 782.1,611.6 851.4,680.9 863.5,680.9 871.2,688.6 871.2,713.4 U2.1
N$22: R8.1 U2.5 | length 133.1
  Top w15: U2.5 948.39,838.39 965,855 965,900 R8.1
N$23: C7.1 L2.1 U2.3 | length 56.8
  Top w15: U2.3 922.8,667.2 930,660
  other v1: 930,585 930,615 930,645 1020,805 1020,830 1020,860
N$24: C7.2 R8.2 | length 60
  Top w15: R8.2 C7.2
N$25: R23.1 U2.8 | length 177
  Top w16: R23.1@768.5,723.4 R23.1@768.5,725.5 ; R23.1 R23.1@768.5,725.5 ; U2.8@871.61,806.61 U2.8 866.13,810.7 815.1,810.7 803,798.6 803,760 R23.1@768.5,725.5
N$26: R13.1 USB2.A5 | length 137.5
  Top w8: USB2.A5 374.21,1549.21 R13.1
N$27: C47.2 R20.2 R23.2 R24.2 | length 175.4
  Top w24: C47.2 708.5,843.9 R24.2 R23.2 710,726 R20.2
N$44: J10.3 R18.1 | length 1966.3
  Top w8: J10.3 261.8,1908.2 420,1750 770,1750 915,1605 v1(915,1575) ; R18.1 v1(1500,1120)
  Bottom w8: v1(915,1575) 915,1375 1020,1270 1145,1270 1205,1330 1450,1330 1510,1270 1510,1130 v1(1500,1120)
N$45: J10.4 R19.1 | length 1947.9
  Top w8: J10.4 361.8,1833.2 425,1770 790,1770 940,1620 v1(940,1600) ; R19.1 1557.5,1120 v1(1565,1127.5)
  Bottom w8: v1(940,1600) 940,1375 1030,1285 1135,1285 1195,1345 1460,1345 1525,1280 1525,1167.5 v1(1565,1127.5)
N$55: 
N$56: 
OUT1: C4.2 C45.2 C46.2 C47.1 L2.2 L6.1 R24.1 | length 1069.8
  Top w24: R24.1 768.5,843.9 C47.1 820,845 850,875 v1(850,895)
  Bottom w24: v1(850,895) 850.4,895.4 903.1,895.4 906.4,898.7 906.4,899.8 960.3,953.7 1257.3,953.7 1325.7,885.3 1325.7,626.1 1293.6,594 1231,594 v1(1230,595)
PA02_AIN0_A0: PC4.1 U3.19 U5.3 | length 1714.3
  Top w8: U5.3 1531.1,1356.1 v1(1535,1360) ; v1(1995,1175) 2000,1170 PC4.1 U3.19
  Bottom w8: v1(1535,1360) 1570,1325 1570,1240 1635,1175 v1(1995,1175)
PA03_AREFA: PC1.8 U3.16 U5.4 | length 1105
  Top w8: U3.16 940,1940 PC1.8 1075,1725 v1(1075,1560) ; U5.4 1510.79,1375.79 v1(1520,1385)
  Bottom w8: v1(1075,1560) 1095,1540 1095,1505 1210,1390 1515,1390 v1(1520,1385)
PA04_AIN4_A3: PC4.4 U3.22 U5.9 | length 2087.2
  Top w8: U5.9 1524.21,1474.21 1550,1500 1930,1500 2060,1370 2060,305 2095,270 2230,270 PC4.4 U3.22
PA05_AIN5_A4: PC4.5 U3.23 U5.10 | length 2185.6
  Top w8: U5.10 1518.9,1493.9 1540,1515 1940,1515 2080,1375 2080,320 2110,290 2310,290 PC4.5 U3.23
PA6_W8: PC1.1 U3.9 U5.11 | length 560.7
  Top w8: U5.11 1503.58,1513.58 1550,1560 1550,1850 PC1.1 1640,1940 U3.9
PA7_W9: PC1.2 U3.10 U5.12 | length 518.4
  Top w8: U5.12 1493.27,1533.27 1530,1570 1530,1870 PC1.2 1540,1940 U3.10
PA08_TCC0-W0/4: PC2.5 U3.5 U5.13 | length 1006.7
  Top w8: U5.13 1458.27,1578.27 1505,1625 v1(1505,1750) ; PC2.5 U3.5
  Bottom w8: v1(1505,1750) 1505,1765 1535,1795 2050,1795 2100,1845 PC2.5
PA09_TCC0-W1/3: PC2.4 U3.4 U5.14 | length 1168
  Top w8: U5.14 1438.58,1588.58 1475,1625 v1(1475,1775) ; PC2.4 U3.4
  Bottom w8: v1(1475,1775) 1475,1740 1490,1725 1515,1725 1570,1780 2080,1780 PC2.4
PA10_TCC0-W2/TX: PC2.2 U3.2 U5.15 | length 1359
  Top w8: U5.15 1418.9,1593.9 1450,1625 v1(1450,1750) ; PC2.2 U3.2
  Bottom w8: v1(1450,1750) 1450,1730 1470,1710 1525,1710 1580,1765 2265,1765 PC2.2
PA11_TCC0-W3/RX: PC2.1 U3.1 U5.16 | length 1450.1
  Top w8: U5.16 1399.21,1599.21 1420,1620 v1(1420,1725) ; PC2.1 U3.1
  Bottom w8: v1(1420,1725) 1450,1695 1535,1695 1590,1750 2350,1750 PC2.1
PA12_MISO: U3.38 U5.21 | length 1761.6
  Top w8: v1(1285,1690) 1285,1630 1300.79,1614.21 U5.21 ; v1(2200,1625) 2200,1270 2270,1200 U3.38
  Bottom w8: v1(1285,1690) 1420,1690 1485,1625 v1(2200,1625)
PA14_TCC0-W4/2: PC2.3 U3.3 U5.23 | length 1417.7
  Top w8: U5.23@1260.83,1560.83 U5.23 1261.42,1796.42 v1(1265,1800) ; v1(2035,1850) 2250,1850 PC2.3 U3.3
  Bottom w8: v1(1265,1800) 1275,1810 1995,1810 v1(2035,1850)
PA15_TCC0-W5/5: PC2.6 U3.6 U5.24 | length 1150.1
  Top w8: v1(1240,1815) 1241.73,1813.27 U5.24 ; PC2.6 U3.6
  Bottom w8: v1(1240,1815) 1250,1825 1925,1825 PC2.6
PA16_W11: PC1.4 U3.12 U5.25 | length 533.5
  Top w8: U5.25 1214.17,1834.17 1275,1895 1300,1895 PC1.4 1340,1940 U3.12
PA17_W13: PC1.6 R7.1 U3.14 U5.26 | length 1486.6
  Top w8: PC1.6 1140,1940 U3.14 ; v1(1187.5,1750) 1185,1747.5 1185,1520 1191.42,1513.58 U5.26
  Top w10: R7.1 315,1795 v1(350,1760)
  Bottom w8: v1(350,1760) 1065,1760 ; PC1.6 1075,1875 1075,1770 ; v1(1187.5,1750) 1172.5,1735 1115,1735 1090,1760 1085,1760 ; 1065,1760 1075,1770 ; 1065,1760 1075,1760 ; 1075,1760 1085,1760 ; 1075,1760 1075,1770 ; 1075,1770 1085,1760
PA18_W10: PC1.3 U3.11 U5.27 | length 755.5
  Top w8: v1(1170,1775) 1162.5,1767.5 1162.5,1522.5 1191.1,1493.9 U5.27 ; v1(1350,1785) 1350,1850 PC1.3 1440,1940 U3.11
  Bottom w8: v1(1170,1775) 1340,1775 v1(1350,1785)
PA19_W12: PC1.5 U3.13 U5.28 | length 608.3
  Top w8: U5.28 1185.79,1474.21 1147.5,1512.5 1147.5,1842.5 1200,1895 PC1.5 1240,1940 U3.13
PA20_TCC0-W6/6: PC2.7 U3.7 U5.29 | length 1315.6
  Top w8: v1(1125,1765) 1125,1510 1180.47,1454.53 U5.29 ; PC2.7 U3.7
  Bottom w8: v1(1125,1765) 1125,1795 1170,1840 1840,1840 PC2.7
PA21_W7: PC2.8 U3.8 U5.30 | length 1306
  Top w8: v1(1100,1845) 1100,1510 1175.16,1434.84 U5.30 ; PC2.8 U3.8
  Bottom w8: v1(1100,1845) 1110,1855 1760,1855 1800,1895 PC2.8
PA27_TX_LED: R43.1 U5.39 | length 1336.3
  Top w8: R43.1 360,1125 360,1180 510,1330 640,1330 710,1400 847.5,1400 v1(867.5,1380) ; v1(1035,1150) 1191.21,1150 1281.1,1239.89 U5.39
  Bottom w8: v1(867.5,1380) 867.5,1372.5 1035,1205 v1(1035,1150)
PA30_SWCLK/TX: R10.1 R18.2 U5.45 | length 420.4
  Top w8: U5.45 1399.21,1255.79 R18.2 1505,1150 1700,1150 R10.1
PA31_SWDIO/RX: R9.1 R19.2 U5.46 | length 385.2
  Top w8: U5.46 1418.9,1261.1 1470,1210 1510,1210 R19.2 1555,1165 1715,1165 R9.1
PB02_AIN10_A5: PC4.6 U3.24 U5.47 | length 2145.5
  Top w8: U5.47 1438.58,1266.42 1480,1225 1575,1225 1600,1200 v1(1690,1200) ; v1(2105,1200) 2100,1195 2100,325 2115,310 2390,310 PC4.6 U3.24
  Bottom w8: v1(1690,1200) v1(2105,1200)
PB03_RX_LED: R44.1 U5.48 | length 1440.8
  Top w8: R44.1 500,1345 630,1345 700,1415 v1(890,1415) ; U5.48 1458.27,1271.73 1470,1260 v1(1485,1260)
  Bottom w8: v1(890,1415) 890,1375 1010,1255 1155,1255 1215,1315 1430,1315 v1(1485,1260)
PB08_AIN2_A1: PC4.2 U3.20 U5.7 | length 1887.4
  Top w8: U5.7 1534.84,1434.84 1570,1470 1910,1470 2020,1360 2020,280 PC4.2 U3.20
PB09_AIN3_A2: PC4.3 U3.21 U5.8 | length 1991.7
  Top w8: U5.8 1529.53,1454.53 1560,1485 1920,1485 2040,1365 2040,290 2080,250 2155,250 2200,205 PC4.3 U3.21
PB10_MOSI: U3.34 U5.19 | length 1749.3
  Top w8: v1(1337.5,1640) 1340.16,1637.34 U5.19 ; v1(2175,1575) 2170,1570 2170,1275 2295,1150 2550,1150 U3.34
  Bottom w8: v1(1337.5,1640) 1420,1640 1485,1575 v1(2175,1575)
PB11_SCK: U3.37 U5.20 | length 1729.4
  Top w8: v1(1307.5,1665) 1307.5,1637.5 1320.47,1624.53 U5.20 ; v1(2150,1600) 2150,1270 2320,1100 U3.37
  Bottom w8: v1(1307.5,1665) 1420,1665 1485,1600 v1(2150,1600)
PB22_TXD: U5.37 UART.2 | length 1671.6
  Top w8: v1(1235,1235) 1235,1275 1241.73,1281.73 U5.37 ; v1(2400,940) 2400,790 2525,665 UART.2
  Bottom w8: v1(1235,1235) 1250,1235 1410,1075 2025,1075 2160,940 v1(2400,940)
PB23_RXD: U5.38 UART.1 | length 1611.4
  Top w8: v1(1260,1255) 1261.42,1256.42 U5.38 ; v1(2425,965) 2425,800 2481.89,743.11 UART.1
  Bottom w8: v1(1260,1255) 1260,1250 1420,1090 2035,1090 2160,965 v1(2425,965)
PWR_IN: C5.+ C9.2 C22.1 L1.2 R21.2 U2.2 | length 154.9
  Top w15: 860,645 897.2,682.2 ; 870,640 897.2,667.2 897.2,672.2 ; 885,660 897.2,672.2 ; U2.2 897.2,682.2 ; 897.2,672.2 897.2,682.2
RESET: J10.5 PC5.6 R11.1 RESET1.2 RST1.- U3.30 U3.36 U5.40 | length 6181.4
  Top w8: J10.5 461.8,2003.2 420,2045 230,2045 210,2025 210,1935 410,1735 750,1735 v1(885,1600) ; RST1.- 570,95 675,200 780,200 ; RESET1.2 860,145 805,200 800,200 ; v1(1010,1125) 1191.96,1125 1300.79,1233.82 U5.40 ; U3.30 PC5.6 1300,350 ; v1(1365.9,592.8) 1365,591.9 1365,410 1315,360 1310,360 ; v1(1560,925) 1560,1005 1615,1060 R11.1 ; v1(2375,800) 2375,975 2400,1000 U3.36 ; 780,200 790,210 ; 780,200 790,200 ; 790,200 800,200 ; 790,200 790,210 ; 790,210 800,200 ; 790,210 790,265 800,275 940,275 1025,360 1290,360 ; 1290,360 1300,350 ; 1290,360 1300,360 ; 1300,350 1310,360 ; 1300,350 1300,360 ; 1300,360 1310,360
  Bottom w8: v1(885,1600) 840,1555 840,1375 1010,1205 v1(1010,1125) 1135,1125 1335,925 1355,925 ; U3.30 U3.30@1315,100 ; v1(1365.9,592.8) 1366.5,593.4 1366.5,916.5 ; v1(2375,800) 2070,800 1945,925 v1(1560,925) 1375,925 ; 1355,925 1365,915 1366.5,916.5 ; 1355,925 1365.1,925 ; 1365.1,925 1366.5,923.6 1366.5,916.5 ; 1365.1,925 1375,925 ; 1366.5,916.5 1375,925
SCL: I2C..1 I2C...1 PC1.10 R3.1 U3.18 U5.32 | length 2743.4
  Top w8: U3.18 740,1940 PC1.10 775,1825 925,1825 1000,1750 1000,1525 R3.1 v1(1055,1495) 1070,1495 1169.53,1395.47 U5.32 ; I2C...1 1895,745 1930,780 1930,1105 v1(1905,1130)
  Bottom w8: v1(1055,1495) 1055,1490 1185,1360 1470,1360 1540,1290 1540,1220 1630,1130 v1(1905,1130) ; I2C...1 I2C..1
SDA: I2C..2 I2C...2 PC1.9 R4.2 U3.17 U5.31 | length 2756.8
  Top w8: U3.17 840,1940 PC1.9 860,1840 935,1840 1030,1745 R4.2 v1(1057.5,1532.5) 1060,1530 1060,1525 1169.84,1415.16 U5.31 ; I2C...2 1895,665 1950,720 1950,1132.5 v1(1937.5,1145)
  Bottom w8: v1(1057.5,1532.5) 1080,1510 1080,1495 1200,1375 1480,1375 1555,1300 1555,1230 1630,1155 1927.5,1155 v1(1937.5,1145) ; I2C...2 I2C..2
USB5V: D5.2 D10.2 F1.2 Q16.3
  other v1: 500,1175 500,1200 510,1625 510,1650
USB_D+: L3.3 U5.34 | length 644.8
  Top w8: L3.3 645.77,1463.27 655,1472.5 902.5,1472.5 975,1400 1085,1400 1128.9,1356.1 U5.34
USB_D-: L3.2 U5.33 | length 642.8
  Top w8: L3.2 648.27,1496.73 655,1490 905,1490 980,1415 1095,1415 1134.21,1375.79 U5.33
V_USB: F1.1 TP7.T USB2.A4_B9 USB2.B4_A9 | length 161.8
  Top w22: USB2.B4_A9 279.49,1405.51 v1(280,1405) v1(305,1405) ; USB2.A4_B9 284.49,1594.49 v1(290,1600) 300,1610 v1(310,1610)
  Bottom w20: TP7.T 300,1620 v1(310,1610)
pads on no net: J1.6 J1.7 J1.8 PC5.8 TP1.T TP2.T U3.32 U5.22 U5.41 USB2.A8 USB2.B8

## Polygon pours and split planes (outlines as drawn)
V_USB on Top "Polygon_1_Net_V_USB" (solid, remove dead copper, pour order 3): 383,1673 308.76,1673 282,1646.24 282,1611.24 277,1606.24 277,1588.76 283.76,1582 356.24,1582 383,1608.76
N$10 on Top "Polygon_1_Net_N$10" (solid, remove dead copper, pour order 23): 536.5,564 471,564 471,381 584,381 584,454 536.5,454
5V on Top "Polygon_1_Net_5V" (solid, remove dead copper, pour order 21): 1078.34,1016 638.34,1016 566,1088.34 566,1096.66 618.34,1149 801.41,1149 826,1173.59 826,1216.66 838.34,1229 851.66,1229 976.66,1104 1281.66,1104 1374,1011.66 1374,691 1263.34,691 1251,703.34 1251,746.66 1266,761.66 1266,958.34 1258.34,966 1098.34,966 1091,973.34 1091,1003.34
OUT1 on Top "Polygon_1_Net_OUT1" (solid, remove dead copper, pour order 14): 1031,684 1206.66,684 1226.66,664 1301.66,664 1319,646.66 1319,558.34 1291.66,531 1053.34,531 1031,553.34
N$23 on Top "Polygon_2_Net_N$23" (solid, remove dead copper, pour order 10): 1003.34,781 1196.66,781 1224,808.34 1224,846.66 1201.66,869 1106.66,869 1089,886.66 1089,916.66 1076.66,929 1038.34,929 1026,916.66 1026,901.66 991,866.66 991,793.34
N$23 on Top "Polygon_1_Net_N$23" (solid, remove dead copper, pour order 0): 916,669 941.66,669 954,656.66 954,578.34 946.66,571 922.53,571 916,584.06
PWR_IN on Top "Polygon_1_Net_PWR_IN" (solid, remove dead copper, pour order 17): 904,496 546,496 546,558.6 526,583.6 526,704 594,704 594.09,600.53 ccw(c610.77,600.57) 610.77,583.89 788.23,583.89 873.34,669 904,669
EXT_PWR on Top "Polygon_1_Net_EXT_PWR" (solid, remove dead copper, pour order 6): 624,270.48 624,194.52 610.48,181 465.75,181 471.1,267.62 487.48,284 610.48,284
USB5V on Top "Polygon_3_Net_USB5V" (solid, remove dead copper, pour order 8): 525,1596 468.34,1596 446,1618.34 446,1653.34 421,1678.34 421,1706.66 438.34,1724 556.66,1724 574,1706.66 574,1613.34 556.66,1596
USB5V on Top "Polygon_1_Net_USB5V" (solid, remove dead copper, pour order 1): 546.66,1151 488.34,1151 476,1163.34 476,1206.66 488.34,1219 546.66,1219 559,1206.66 559,1163.34
3V3 on Top "Polygon_3_Net_3V3" (solid, remove dead copper, pour order 18): 1916.66,556 1793.34,556 1771,578.34 1771,1010.48 1784.52,1024 1850.48,1024 1864,1010.48 1864,634.69 1879.69,619 1911.66,619 1929,601.66 1929,568.34
3V3 on Top "Polygon_2_Net_3V3" (solid, remove dead copper, pour order 15): 1126.66,1274 936.66,1274 826.66,1384 753.34,1384 741,1371.66 741,1268.34 767.17,1242.17 771,1238.34 771,1183.34 778.34,1176 791.66,1176 799,1183.34 799,1233.34 821.66,1256 848.34,1256 918.34,1186 1126.66,1186 1139,1198.34 1139,1261.66
GND on Top "Polygon_11_Net_GND" (solid, remove dead copper, pour order 5): 716.24,1718 653.76,1718 642,1706.24 642,1558.76 653.76,1547 721.24,1547 728,1553.76 728,1706.24
GND on Top "Polygon_10_Net_GND" (solid, remove dead copper, pour order 9): 1725,1019 1608.34,1019 1586,996.66 1586,893.34 1598.34,881 1736.66,881 1749,893.34 1749,1006.66 1736.66,1019 1730,1019
GND on Top "Polygon_9_Net_GND" (solid, remove dead copper, pour order 19): -29,1704 129,1704 129,1321 -29,1321
GND on Top "Polygon_6_Net_GND" (solid, remove dead copper, pour order 4): 670,1289 696.66,1289 729,1256.66 729,1183.34 711.66,1166 648.34,1166 636,1178.34 636,1271.66 653.34,1289
GND on Top "Polygon_5_Net_GND" (solid, remove dead copper, pour order 12): 909,994 593.34,994 561,961.66 561,923.34 573.34,911 663.34,911 693.34,881 791.66,881 826.66,916 876.66,916 909,948.34
GND on Top "Polygon_4_Net_GND" (solid, remove dead copper, pour order 2): 1123.34,944 1236.66,944 1249,931.66 1249,893.34 1236.66,881 1123.34,881 1106,898.34 1106,926.66
GND on Top "Polygon_3_Net_GND" (solid, remove dead copper, pour order 25): -31,2131 2731,2131 2731,-31 -31,-31
GND on Top "Polygon_2_Net_GND" (solid, remove dead copper, pour order 7): 1015,1296 1086.66,1296 1104,1313.34 1104,1361.66 1076.66,1389 928.34,1389 916,1376.66 916,1313.34 933.34,1296
GND on Top "Polygon_1_Net_GND" (solid, remove dead copper, pour order 24): 863.34,784 981.66,784 1019,746.66 1019,541.66 1041.66,519 1306.66,519 1324,501.66 1324,408.7 1286.3,371 1016.66,371 986.66,341 664.15,341 654,351.15 654,350.34 591,413.34 591,479 911,479 911,546.66 923.34,559 953.34,559 966,571.66 966,668.34 941,693.34 941,743.34 938.34,746 858.34,746 851,753.34 851,771.66
V_USB on Bottom "Polygon_2_Net_V_USB" (solid, remove dead copper, pour order 11): 305,1423 273.76,1423 262,1411.24 262,1383.76 273.76,1372 371.24,1372 403,1403.76 403,1636.24 391.24,1648 283.76,1648 272,1636.24 272,1588.76 283.76,1577 323.76,1577 342,1558.76 342,1451.24 313.76,1423
N$23 on Bottom "Polygon_3_Net_N$23" (solid, remove dead copper, pour order 13): 998.34,879 1051.66,879 1064,866.66 1064,658.41 971.72,561 918.34,561 896,583.34 896,671.66 961,736.66 961,811.66 986,836.66 986,866.66
USB5V on Bottom "Polygon_2_Net_USB5V" (solid, remove dead copper, pour order 16): 486,1169.52 486,1650.48 499.52,1664 560.48,1664 574,1650.48 574,1169.52 560.48,1156 499.52,1156
3V3 on Bottom "Polygon_1_Net_3V3" (solid, remove dead copper, pour order 22): 1401.66,1049 2011.66,1049 2151.64,909.02 2674,914.04 2674,821 2078.34,821 1948.34,951 1338.34,951 1148.34,1141 1068.34,1141 1056,1153.34 1056,1226.66 1068.34,1239 1211.66,1239
GND on Bottom "Polygon_8_Net_GND" (solid, remove dead copper, pour order 20): -29,1704 129,1704 129,1321 -29,1321
GND on Bottom "Polygon_7_Net_GND" (solid, remove dead copper, pour order 26): -31,-56 81,-56 81,-31 2731,-31 2731,2131 -31,2131

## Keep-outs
Keep-Out Layer:
  the board outline again, w8

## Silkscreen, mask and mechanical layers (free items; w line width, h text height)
Top Overlay:
  drawing of 17611 lines, arcs and shapes, not listed
  text "seeed.cc" at 2210.8,1276.8 h42.5 r90
Bottom Overlay:
  drawing of 18059 lines, arcs and shapes, not listed
  text "Seeeduino Cortex-M0+" at 1865,1270 h59.5
  text "v1.0 02/11/2019" at 1865,1180 h42.5
  text "Designed by Seeed" at 1865,1095 h42.5
  text "Designer: Weifeng Zeng" at 1865,1005 h42.5
  text "www.seeedstudio.com" at 1865,930 h42.5
Dimension:
  lines w0: -5,0 5,0 ; 0,-5 0,5 ; 2600,1610.71 ccw(c2650,1610.71) 2614.65,1575.35 2700,1490
  lines w1: 900.36,0 cw(c900.36,25) 882.68,7.32 857.32,32.68 ccw(c839.64,15) 839.64,40 710.36,40 ccw(c710.36,15) 692.68,32.68 667.32,7.32 cw(c649.64,25) 649.64,0 50,0 ; 2700,1490 2600,1590 2600,2000 ; 0,50 ccw(c50,50) 50,0 ; 0,50 ccw(c50,50) 50,0 ; 0,50 ccw(c50,50) 50,0 ; 0,50 ccw(c50,50) 50,0 ; 0,50 0,2050 ; 0,2050 cw(c50,2050) 50,2100 ; 0,2050 cw(c50,2050) 50,2100 ; 0,2050 cw(c50,2050) 50,2100 ; 50,2100 2500,2100 ; 2500,2100 cw(c2500,2000) 2600,2000 ; 2500,2100 cw(c2500,2000) 2600,2000 ; 2500,2100 cw(c2500,2000) 2600,2000 ; 63.11,236.42 ccw(c73.11,236.42) 73.11,226.42 131.85,226.42 ccw(c131.85,236.42) 141.85,236.42 141.85,295.16 ccw(c131.85,295.16) 131.85,305.16 73.11,305.16 ccw(c73.11,295.16) 63.11,295.16 63.11,236.42
  lines w8: 900.36,0 2550,0 ; 2700,1490 2700,200 2600,100 2600,50 ; 2550,0 ccw(c2550,50) 2600,50 ; 2550,0 ccw(c2550,50) 2600,50 ; 2550,0 ccw(c2550,50) 2600,50 ; 2550,0 ccw(c2550,50) 2600,50
Reference:
  lines w1: 600,1980 600,2020 ; 920,2000 960,2000 ; 940,1980 940,2020 ; 1020,2000 1060,2000 ; 1040,1980 1040,2020 ; 1080,100 1120,100 ; 1100,80 1100,120 ; 1120,2000 1160,2000 ; 1140,1980 1140,2020 ; 1180,100 1220,100 ; 1200,80 1200,120 ; 1220,2000 1260,2000 ; 1240,1980 1240,2020 ; 1280,100 1320,100 ; 1300,80 1300,120 ; 1320,2000 1360,2000 ; 1340,1980 1340,2020 ; 1380,100 1420,100 ; 1400,80 1400,120 ; 1420,2000 1460,2000 ; 1440,1980 1440,2020 ; 1480,100 1520,100 ; 1500,80 1500,120 ; 1520,2000 1560,2000 ; 1540,1980 1540,2020 ; 1580,100 1620,100 ; 1600,80 1600,120 ; 1620,2000 1660,2000 ; 1640,1980 1640,2020 ; 1680,100 1720,100 ; 1700,80 1700,120 ; 1780,100 1820,100 ; 1780,2000 1820,2000 ; 1800,80 1800,120 ; 1800,1980 1800,2020 ; 1880,2000 1920,2000 ; 1900,1980 1900,2020 ; 1980,100 2020,100 ; 1980,2000 2020,2000 ; 2000,80 2000,120 ; 2000,1980 2000,2020 ; 2080,100 2120,100 ; 2080,2000 2120,2000 ; 2100,80 2100,120 ; 2100,1980 2100,2020 ; 2180,100 2220,100 ; 2180,1000 2220,1000 ; 2180,1100 2220,1100 ; 2180,1200 2220,1200 ; 2180,2000 2220,2000 ; 2200,80 2200,120 ; 2200,980 2200,1020 ; 2200,1080 2200,1120 ; 2200,1180 2200,1220 ; 2200,1980 2200,2020 ; 2280,100 2320,100 ; 2280,1000 2320,1000 ; 2280,1100 2320,1100 ; 2280,1200 2320,1200 ; 2280,2000 2320,2000 ; 2300,80 2300,120 ; 2300,980 2300,1020 ; 2300,1080 2300,1120 ; 2300,1180 2300,1220 ; 2300,1980 2300,2020 ; 2380,100 2420,100 ; 2380,2000 2420,2000 ; 2400,80 2400,120 ; 2400,1980 2400,2020 ; 2480,100 2520,100 ; 2480,1000 2520,1000 ; 2480,1100 2520,1100 ; 2480,1200 2520,1200 ; 2480,2000 2520,2000 ; 2500,80 2500,120 ; 2500,980 2500,1020 ; 2500,1080 2500,1120 ; 2500,1180 2500,1220 ; 2500,1980 2500,2020 ; 2580,300 2620,300 ; 2580,1000 2620,1000 ; 2580,1100 2620,1100 ; 2580,1200 2620,1200 ; 2600,980 2600,1020 ; 2600,1080 2600,1120 ; 2600,1180 2600,1220 ; 0,0 2600,0 2600,100 2700,200 2700,1490 2600,1590 2600,2040 2540,2100 0,2100 0,0
dxf:
  lines w1: 600,0 600,-100 950,-100 950,0 ; 2450,-100 2450,0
